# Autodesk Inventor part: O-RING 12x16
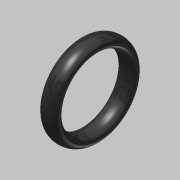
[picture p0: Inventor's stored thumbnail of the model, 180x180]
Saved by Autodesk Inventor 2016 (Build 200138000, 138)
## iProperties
Created: 2020-02
Part Number: O-RING 12x16
Material: 고무
Document SubType Name: Modeling
Designer: mduedu
Density: 1 g/cm^3
Appearance: 고무 - 검은색 - 버전 1.1
Author: mduedu
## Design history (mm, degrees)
sketch "스케치1"
  geometry: L1 (-2.24, 0)-(2.24, 0) reference; L2 (-1.6, 7)-(1.6, 7); L3 (0, 8)-(0, 6); 6 further points; 1 other entity
  constraints: 4 end point, 3 coincident, 2 midpoint, 1 horizontal, 1 vertical, 1 vertical alignment, 6 other
  dimensions: "d0" = 1.6 distance of point (1.6, 7) point (0, 7); "d2" = 12 diameter of point (0, 6) L1; "d3" = 16 diameter of point (0, 8) L1
revolve "회전1" sketch "스케치1" stored, may be unused: angle "d4" = 90 deg
node "솔리드1"
